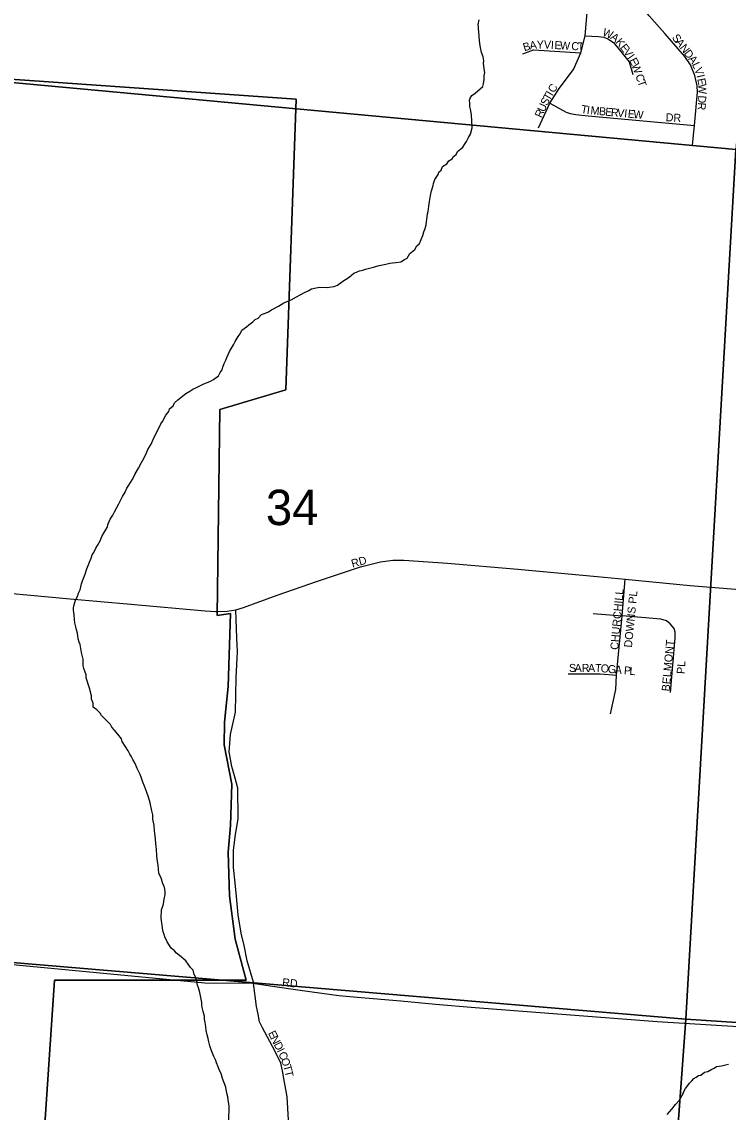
# Model space of a CAD drawing. Extents: x 8.5 to 81.5, y -1.2 to 22.4.
# Drawn here: x 54.054 to 54.89, y 16.084 to 17.374 of the extents above; entities that cross this region are included whole.
import ezdxf

# ---------------------------------------------------------------- set-up
doc = ezdxf.new("R2010")
doc.units = 0
for name, color, linetype in [('GM_X_City_Street', 7, 'Continuous'), ('GM_X_City_Street_Text', 7, 'Continuous'), ('GM_X_Corporation', 7, 'Continuous'), ('GM_X_Minor_River', 7, 'Continuous'), ('GM_X_Section', 7, 'Continuous'), ('GM_X_Section_Text', 7, 'Continuous')]:
    doc.layers.add(name, color=color, linetype=linetype)

msp = doc.modelspace()

# ---------------------------------------------------------------- linework, layer by layer
at = {"layer": 'GM_X_City_Street'}
for points in [[(54.6655, 17.2485), (54.6786, 17.2776), (54.6897, 17.2952), (54.7068, 17.3174), (54.7156, 17.3372), (54.7207, 17.3574), (54.7297, 17.4641), (54.7355, 17.521), (54.7449, 17.623), (54.7556, 17.7393)], [(54.8478, 17.228), (54.85, 17.2514), (54.8534, 17.2907), (54.853, 17.2984), (54.8505, 17.3103), (54.8453, 17.323), (54.8384, 17.333), (54.8148, 17.3603), (54.7962, 17.3811), (54.787, 17.3926), (54.7841, 17.3979), (54.782, 17.4049), (54.7813, 17.4114), (54.7851, 17.459)], [(54.7207, 17.3574), (54.7363, 17.3564), (54.7425, 17.3556), (54.7476, 17.3538), (54.754, 17.3493), (54.7726, 17.3267), (54.7771, 17.3116)], [(54.647, 17.336), (54.6596, 17.341), (54.7156, 17.3372)], [(54.6786, 17.2776), (54.6981, 17.2672), (54.7028, 17.2656), (54.7097, 17.2643), (54.7243, 17.2629), (54.85, 17.2514)], [(54.2835, 16.6763), (54.2843, 16.6763), (54.2967, 16.6768), (54.3073, 16.6781), (54.3163, 16.6811), (54.3562, 16.6956), (54.404, 16.712), (54.4546, 16.7291), (54.4784, 16.7352), (54.4929, 16.7371), (54.5061, 16.7369), (54.5575, 16.7336), (54.6408, 16.7262), (54.7348, 16.7175), (54.768, 16.7144), (54.8448, 16.7072), (54.9375, 16.6996), (55.0463, 16.6916), (55.0916, 16.6882), (55.1529, 16.6837), (55.27, 16.6737), (55.2474, 16.6753), (55.3632, 16.666), (55.4729, 16.6578)], [(53.8549, 16.7151), (53.9257, 16.7085), (53.9911, 16.7024), (54.1111, 16.6913), (54.183, 16.6848), (54.271, 16.6769), (54.2835, 16.6763)], [(54.7506, 16.5551), (54.7568, 16.5838), (54.7577, 16.6008), (54.7644, 16.6711), (54.768, 16.7144)], [(54.3281, 16.2365), (54.3279, 16.2377), (54.3207, 16.2631), (54.3171, 16.2812), (54.3134, 16.2956), (54.3098, 16.3174), (54.308, 16.3391), (54.3062, 16.3554), (54.3044, 16.3735), (54.3044, 16.3934), (54.3062, 16.4096), (54.3098, 16.4314), (54.3094, 16.4672), (54.3063, 16.4791), (54.3025, 16.493), (54.2994, 16.5103), (54.2999, 16.5202), (54.3007, 16.5309), (54.3067, 16.5571), (54.3075, 16.5983), (54.3092, 16.6284), (54.3084, 16.6448), (54.3073, 16.6781)], [(54.7299, 16.6739), (54.7644, 16.6711)], [(54.8214, 16.5803), (54.827, 16.6451), (54.8273, 16.6519), (54.8261, 16.656), (54.8211, 16.6616), (54.8169, 16.6651), (54.8103, 16.6673), (54.7644, 16.6711)], [(54.7004, 16.6027), (54.7384, 16.6027), (54.7577, 16.6008)], [(54.0135, 16.2615), (54.2704, 16.2369), (54.3281, 16.2364), (54.3302, 16.236)], [(54.4253, 15.8653), (54.4252, 15.8654), (54.4058, 15.9193), (54.4003, 15.9374), (54.3931, 15.9591), (54.3895, 15.9754), (54.3859, 15.9862), (54.3804, 16.0025), (54.3786, 16.0134), (54.3768, 16.0224), (54.375, 16.0315), (54.3732, 16.0441), (54.3696, 16.0749), (54.3678, 16.102), (54.3641, 16.1237), (54.3623, 16.1328), (54.3605, 16.1418), (54.3533, 16.1563), (54.3388, 16.1835), (54.3352, 16.1907), (54.3334, 16.1997), (54.3315, 16.2088), (54.3281, 16.2364), (54.3281, 16.2365)], [(54.3302, 16.236), (54.3478, 16.2332), (54.3861, 16.2278), (54.4292, 16.2221), (54.4506, 16.22), (54.5024, 16.2157), (54.5433, 16.2115), (54.5904, 16.2079), (54.8059, 16.1913), (54.9018, 16.1854), (54.988, 16.1809), (55.2237, 16.1661), (55.3305, 16.1593)]]:
    msp.add_lwpolyline(points, dxfattribs=at)
at = {"layer": 'GM_X_Corporation'}
for points in [[(54.0384, 15.4358), (54.0924, 16.2401), (54.3192, 16.2402), (54.3063, 16.2886), (54.2996, 16.34), (54.2982, 16.3917), (54.3007, 16.4231), (54.3023, 16.4721), (54.2932, 16.5186), (54.2936, 16.5455), (54.2981, 16.5876), (54.3008, 16.6738), (54.285, 16.6714), (54.2884, 16.9152), (54.3663, 16.9386), (54.3787, 17.2825), (53.7076, 17.3294)], [(53.7076, 17.3294), (54.3787, 17.2825), (54.3663, 16.9386), (54.2884, 16.9152), (54.285, 16.6714), (54.3008, 16.6738), (54.2981, 16.5876), (54.2936, 16.5455), (54.2932, 16.5186), (54.3023, 16.4721), (54.3007, 16.4231), (54.2982, 16.3917), (54.2996, 16.34), (54.3063, 16.2886), (54.3192, 16.2402), (54.0924, 16.2401), (54.0384, 15.4358)]]:
    msp.add_lwpolyline(points, dxfattribs=at)
at = {"layer": 'GM_X_Minor_River'}
for points in [[(54.5776, 17.2287), (54.5803, 17.2325), (54.5827, 17.237), (54.585, 17.2411), (54.5867, 17.2487), (54.5865, 17.2571), (54.5859, 17.2635), (54.5855, 17.2662), (54.5849, 17.2708), (54.5842, 17.2738), (54.5839, 17.2773), (54.5836, 17.2811), (54.5844, 17.2837), (54.5863, 17.2867), (54.5906, 17.2897), (54.5964, 17.2945), (54.5995, 17.2975), (54.6003, 17.3005), (54.6012, 17.3058), (54.6012, 17.31), (54.6017, 17.3141), (54.601, 17.3183), (54.6004, 17.3252), (54.6005, 17.3279), (54.5998, 17.3324), (54.598, 17.3378), (54.597, 17.3416), (54.5963, 17.3454), (54.5956, 17.3515), (54.595, 17.3565), (54.5947, 17.3626), (54.5944, 17.3652), (54.5945, 17.3679), (54.5941, 17.3709), (54.595, 17.3762)], [(54.2202, 16.901), (54.2242, 16.9085), (54.2277, 16.913), (54.2285, 16.916), (54.2328, 16.9198), (54.2347, 16.9231), (54.2386, 16.9269), (54.2479, 16.9343), (54.2528, 16.9368), (54.2563, 16.9394), (54.2613, 16.9416), (54.2686, 16.9453), (54.2712, 16.9464), (54.2762, 16.9485), (54.2808, 16.9507), (54.2866, 16.9552), (54.2886, 16.9589), (54.2909, 16.9623), (54.2917, 16.9653), (54.2933, 16.9695), (54.2953, 16.9736), (54.2965, 16.9766), (54.2981, 16.9804), (54.2997, 16.9838), (54.3044, 16.9917), (54.3064, 16.9958), (54.3099, 17.0015), (54.3123, 17.0048), (54.3143, 17.009), (54.3197, 17.013), (54.3224, 17.0153), (54.3274, 17.019), (54.3301, 17.0216), (54.3335, 17.0234), (54.3374, 17.0275), (54.3412, 17.029), (54.3458, 17.0308), (54.3493, 17.033), (54.3577, 17.0374), (54.3639, 17.0414), (54.3727, 17.0451), (54.3788, 17.0487), (54.3831, 17.0509), (54.3892, 17.0539), (54.3934, 17.056), (54.3969, 17.0579), (54.4022, 17.0593), (54.406, 17.06), (54.4151, 17.0598), (54.4178, 17.0601), (54.4235, 17.0608), (54.4273, 17.0622), (54.4338, 17.067), (54.4369, 17.0689), (54.4412, 17.0718), (54.4469, 17.0766), (54.45, 17.0777), (54.4534, 17.0792), (54.4573, 17.0802), (54.4607, 17.0813), (54.4699, 17.0838), (54.4767, 17.0856), (54.4847, 17.0873), (54.4893, 17.0883), (54.4927, 17.0887), (54.4965, 17.0893), (54.5026, 17.09), (54.5069, 17.0929), (54.5099, 17.0944), (54.5131, 17.0997), (54.5189, 17.1045), (54.5212, 17.109), (54.5247, 17.1116), (54.5263, 17.1165), (54.5283, 17.121), (54.5295, 17.1256), (54.5311, 17.1293), (54.5324, 17.1339), (54.5341, 17.1467), (54.5346, 17.1494), (54.535, 17.1528), (54.5355, 17.1558), (54.5363, 17.1615), (54.5376, 17.1683), (54.5389, 17.174), (54.5405, 17.1801), (54.541, 17.1827), (54.5426, 17.1872), (54.5465, 17.1932), (54.5473, 17.1959), (54.55, 17.1985), (54.5516, 17.2026), (54.557, 17.206), (54.5593, 17.2093), (54.5632, 17.2119), (54.5648, 17.2145), (54.5678, 17.2171), (54.5694, 17.2205), (54.5733, 17.2235), (54.576, 17.2257), (54.5776, 17.2287)], [(54.2117, 16.4109), (54.2114, 16.4136), (54.2107, 16.4166), (54.2104, 16.4231), (54.209, 16.4307), (54.2088, 16.4357), (54.2077, 16.4406), (54.2056, 16.4498), (54.2039, 16.4567), (54.2014, 16.4635), (54.1992, 16.4697), (54.197, 16.4743), (54.1956, 16.4789), (54.1938, 16.4835), (54.1905, 16.4907), (54.188, 16.4965), (54.1851, 16.5011), (54.1833, 16.505), (54.1818, 16.5076), (54.1796, 16.5115), (54.1726, 16.5223), (54.1719, 16.5257), (54.1675, 16.5311), (54.163, 16.5361), (54.1604, 16.5396), (54.159, 16.5427), (54.1545, 16.547), (54.1512, 16.5501), (54.1482, 16.5532), (54.1464, 16.5559), (54.1426, 16.5601), (54.1385, 16.5632), (54.1383, 16.5678), (54.1364, 16.5724), (54.1362, 16.5766), (54.1341, 16.5854), (54.1301, 16.5976), (54.1302, 16.6014), (54.1273, 16.6087), (54.1266, 16.6121), (54.1263, 16.6163), (54.1264, 16.6197), (54.1257, 16.6232), (54.1243, 16.6277), (54.123, 16.6373), (54.1219, 16.64), (54.1205, 16.6438), (54.1198, 16.6506), (54.1184, 16.6545), (54.1177, 16.6583), (54.1167, 16.6629), (54.1164, 16.6667), (54.1157, 16.6724), (54.1151, 16.6777), (54.1151, 16.6808), (54.116, 16.6842), (54.1172, 16.6895), (54.1196, 16.694), (54.1208, 16.6981), (54.1228, 16.7019), (54.1245, 16.7091), (54.1257, 16.7125), (54.1289, 16.7204), (54.1301, 16.7242), (54.1309, 16.7268), (54.1341, 16.7347), (54.1361, 16.7393), (54.1373, 16.7434), (54.1389, 16.746), (54.1413, 16.7513), (54.1436, 16.7543), (54.1464, 16.76), (54.1484, 16.7649), (54.1515, 16.7697), (54.1547, 16.7758), (54.1559, 16.7799), (54.1583, 16.7856), (54.1614, 16.7904), (54.1634, 16.7942), (54.1665, 16.7995), (54.1685, 16.8036), (54.1697, 16.8062), (54.1732, 16.8122), (54.176, 16.8175), (54.178, 16.822), (54.1807, 16.8258), (54.1823, 16.8288), (54.1843, 16.8322), (54.1859, 16.8348), (54.1878, 16.8382), (54.1918, 16.8457), (54.1957, 16.8525), (54.1985, 16.8581), (54.2016, 16.8641), (54.2032, 16.8679), (54.2068, 16.8743), (54.2083, 16.8769), (54.21, 16.8818), (54.2167, 16.8946), (54.2183, 16.8984), (54.2202, 16.901)], [(54.2988, 16.0735), (54.2992, 16.091), (54.2982, 16.0986), (54.2975, 16.1021), (54.2968, 16.1047), (54.2958, 16.1108), (54.2955, 16.1135), (54.2933, 16.1185), (54.2915, 16.1238), (54.2898, 16.1296), (54.2879, 16.1334), (54.2861, 16.1376), (54.2843, 16.1422), (54.2836, 16.1449), (54.2811, 16.1499), (54.2778, 16.1576), (54.2764, 16.1625), (54.2753, 16.1671), (54.2743, 16.1709), (54.2732, 16.1755), (54.2722, 16.1805), (54.2715, 16.1854), (54.2709, 16.19), (54.2702, 16.1938), (54.2699, 16.1973), (54.2685, 16.203), (54.2674, 16.2076), (54.2671, 16.211), (54.2668, 16.2137), (54.2661, 16.2175), (54.2644, 16.2255), (54.263, 16.2312), (54.2619, 16.2343), (54.2609, 16.2381), (54.2598, 16.2431), (54.258, 16.2469), (54.2566, 16.2519), (54.2536, 16.255), (54.2507, 16.2592), (54.2481, 16.2631), (54.2406, 16.2693), (54.2369, 16.272), (54.2347, 16.2747), (54.2306, 16.2779), (54.2258, 16.2856), (54.2233, 16.2913), (54.2222, 16.294), (54.2211, 16.2974), (54.2204, 16.3016), (54.2198, 16.3054), (54.2191, 16.3104), (54.2188, 16.3138), (54.219, 16.3233), (54.2206, 16.3275), (54.2214, 16.3305), (54.2223, 16.3358), (54.2235, 16.3415), (54.2236, 16.3441), (54.2233, 16.3476), (54.2222, 16.3514), (54.2208, 16.3541), (54.2186, 16.3613), (54.2161, 16.3663), (54.2158, 16.372), (54.2151, 16.3759), (54.2145, 16.3808), (54.2138, 16.3869), (54.2133, 16.3953), (54.2129, 16.3979), (54.2123, 16.4021), (54.2117, 16.4109)], [(54.8177, 16.0811), (54.8231, 16.0874), (54.8274, 16.0931), (54.8317, 16.0979), (54.8364, 16.1058), (54.8372, 16.1084), (54.8392, 16.1118), (54.8419, 16.1156), (54.8439, 16.1182), (54.847, 16.1208), (54.8493, 16.1238), (54.852, 16.1253), (54.8547, 16.1271), (54.8574, 16.1278), (54.862, 16.1311), (54.8658, 16.1322), (54.8704, 16.1348), (54.8731, 16.1359), (54.8762, 16.1381), (54.8792, 16.1384), (54.8819, 16.1387), (54.8865, 16.1398), (54.8903, 16.1408)]]:
    msp.add_lwpolyline(points, dxfattribs=at)
at = {"layer": 'GM_X_Section'}
for points in [[(54.0614, 18.3096), (54.9861, 18.2233), (54.8988, 17.2229), (53.9056, 17.3146), (53.9598, 18.0642)], [(53.9056, 17.3146), (54.8988, 17.2229), (54.8397, 16.1939), (53.8407, 16.2781)], [(54.8988, 17.2229), (55.9017, 17.1283), (55.8345, 16.129), (54.8397, 16.1939)], [(54.8397, 16.1939), (54.767, 15.2026), (54.632, 15.2135), (54.5739, 15.4285), (54.511, 15.4861), (54.4715, 15.4998), (54.3017, 15.5169), (54.1688, 15.4759), (54.0565, 15.4235), (53.8996, 15.2768), (53.754, 15.289), (53.8407, 16.2781)], [(55.8345, 16.129), (55.7433, 15.123), (54.767, 15.2026), (54.8397, 16.1939)]]:
    msp.add_lwpolyline(points, close=True, dxfattribs=at)

# ---------------------------------------------------------------- texts
at = {"layer": 'GM_X_City_Street_Text'}
for s, rotation, p in [('W', 337.7771, (54.7402, 17.3581)), ('Y', 0.8931, (54.6633, 17.3423)), ('V', 356.8625, (54.6715, 17.3425)), ('A', 323.1257, (54.7497, 17.3543)), ('K', 309.6293, (54.7559, 17.3497)), ('S', 307.5803, (54.8228, 17.355)), ('A', 307.5861, (54.8269, 17.3497)), ('B', 17.0158, (54.6486, 17.339)), ('A', 8.9545, (54.6555, 17.3411)), ('I', 356.8625, (54.6798, 17.342)), ('E', 356.8625, (54.684, 17.3418)), ('W', 356.8625, (54.6906, 17.3414)), ('C', 356.8625, (54.7039, 17.3407)), ('T', 356.8625, (54.7114, 17.3403)), ('E', 307.9301, (54.7612, 17.3433)), ('V', 307.9379, (54.7653, 17.3381)), ('N', 307.5913, (54.832, 17.3431)), ('D', 307.5779, (54.837, 17.3365)), ('I', 305.4361, (54.7703, 17.3316)), ('E', 295.8932, (54.7725, 17.3286)), ('W', 289.5091, (54.7753, 17.3228)), ('A', 306.9836, (54.8421, 17.3299)), ('L', 294.8782, (54.8468, 17.3237)), ('V', 289.5686, (54.8496, 17.3179)), ('C', 59.4415, (54.6839, 17.2891)), ('C', 289.2259, (54.7798, 17.3103)), ('T', 289.244, (54.7822, 17.3032)), ('I', 283.188, (54.8523, 17.3103)), ('E', 280.9134, (54.8532, 17.3063)), ('W', 271.917, (54.8544, 17.3002)), ('T', 60.0484, (54.6785, 17.2797)), ('I', 59.4037, (54.6818, 17.2855)), ('U', 65.4866, (54.6721, 17.2664)), ('S', 63.1539, (54.6755, 17.2739)), ('T', 350.1155, (54.7151, 17.2664)), ('I', 352.3061, (54.7221, 17.2652)), ('R', 266.0632, (54.8541, 17.2788)), ('D', 266.2601, (54.8546, 17.2871)), ('R', 65.4555, (54.669, 17.2596)), ('M', 354.6012, (54.7266, 17.2646)), ('B', 354.9509, (54.7366, 17.2637)), ('E', 354.9391, (54.7441, 17.263)), ('R', 354.9177, (54.7507, 17.2624)), ('V', 354.9501, (54.7582, 17.2617)), ('I', 354.9243, (54.7665, 17.261)), ('E', 354.952, (54.7707, 17.2606)), ('W', 354.9334, (54.7773, 17.2601)), ('DR', 356.989, (54.8157, 17.2564)), ('RD', 15.5166, (54.4452, 16.7281)), ('CHURCHILL', 84.9367, (54.7597, 16.6306)), ('DOWNS PL', 84.3711, (54.7759, 16.6333)), ('BELMONT', 84.8853, (54.8205, 16.5815)), ('PL', 86.4262, (54.8383, 16.6021)), ('S', 359.9727, (54.7014, 16.6048)), ('A', 359.9563, (54.7081, 16.6048)), ('R', 359.9514, (54.7164, 16.6048)), ('A', 359.9703, (54.7239, 16.6048)), ('T', 358.6614, (54.7322, 16.6048)), ('O', 355.2962, (54.7387, 16.6046)), ('G', 354.5047, (54.747, 16.6039)), ('A', 354.5294, (54.7553, 16.6031)), ('P', 354.5167, (54.7661, 16.6021)), ('L', 354.5286, (54.7727, 16.6015)), ('RD', 353.9946, (54.3616, 16.2331)), ('E', 296.5651, (54.345, 16.1775)), ('N', 296.5651, (54.3479, 16.1715)), ('D', 296.5651, (54.3517, 16.1641)), ('I', 296.5651, (54.3554, 16.1566)), ('C', 294.2721, (54.3572, 16.153)), ('O', 289.6862, (54.3602, 16.1463)), ('T', 285.1002, (54.363, 16.1387)), ('T', 282.8073, (54.3647, 16.1323))]:
    msp.add_text(s, height=0.00947, rotation=rotation, dxfattribs=at).set_placement(p)
at = {"layer": 'GM_X_Section_Text'}
msp.add_text('34', height=0.04186, rotation=0, dxfattribs=at).set_placement((54.3427, 16.7785))

doc.saveas('drawing.dxf')
